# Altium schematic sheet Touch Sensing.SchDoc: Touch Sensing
size A4; DocumentNumber: MB1144; Revision: C-02; SheetNumber: 17; SheetTotal: 25; Project: STM32L476G-EVAL
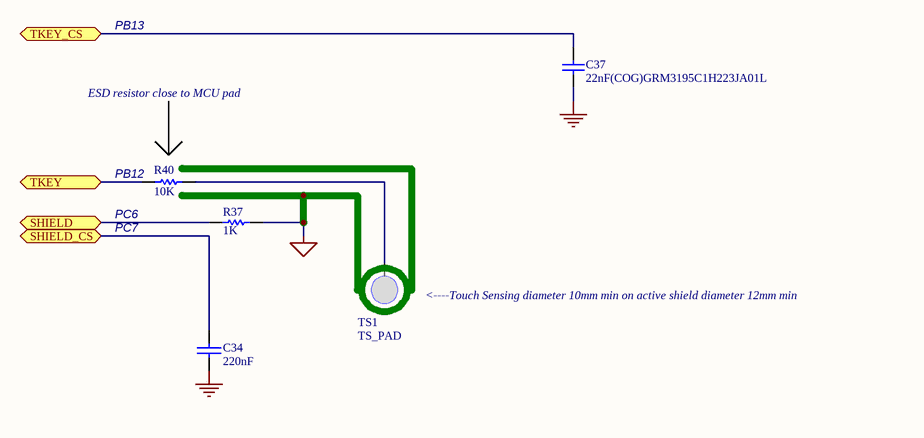
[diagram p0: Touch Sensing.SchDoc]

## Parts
C34  220nF  [0603C]
C37  22nF(COG)GRM3195C1H223JA01L  [1206C]
R37  1K  [0402R]
R40  10K  [0402R]
TS1  TS_PAD  [TS_PAD]

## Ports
SHIELD, SHIELD_CS, TKEY, TKEY_CS

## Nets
GND: C34.1 C37.1
TS_SHIELD: R37.2
SHIELD: R37.1 ; port SHIELD
SHIELD_CS: C34.2 ; port SHIELD_CS
TKEY: R40.1 ; port TKEY
TKEY_CS: C37.2 ; port TKEY_CS
NetR40_2: R40.2 TS1.1

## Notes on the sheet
- PB13
- ESD resistor close to MCU pad
- (near R40) PB12
- (near R40) PC6
- (near R40) PC7
- (near TS1) <----Touch Sensing diameter 10mm min on active shield diameter 12mm min

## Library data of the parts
C34 = CAP: Capacitor; Ordered by: Subcon; ECCN_US/EU: NA
C37 = CAP: Capacitor; Value: 100pF; Ordered by: Subcon; ECCN_US/EU: NA
R37 = Res1: Resistor; Ordered by: Subcon; ECCN_US/EU: NA
R40 = Res1: Resistor; Value: 1K; Ordered by: Subcon; ECCN_US/EU: NA
TS1 = TS_PAD: Ordered by: Subcon; ECCN_US/EU: NA; Assembly: with transparent plastic cover; Comments: touch sensing button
